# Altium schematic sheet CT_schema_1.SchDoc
size 403 x 336 mm
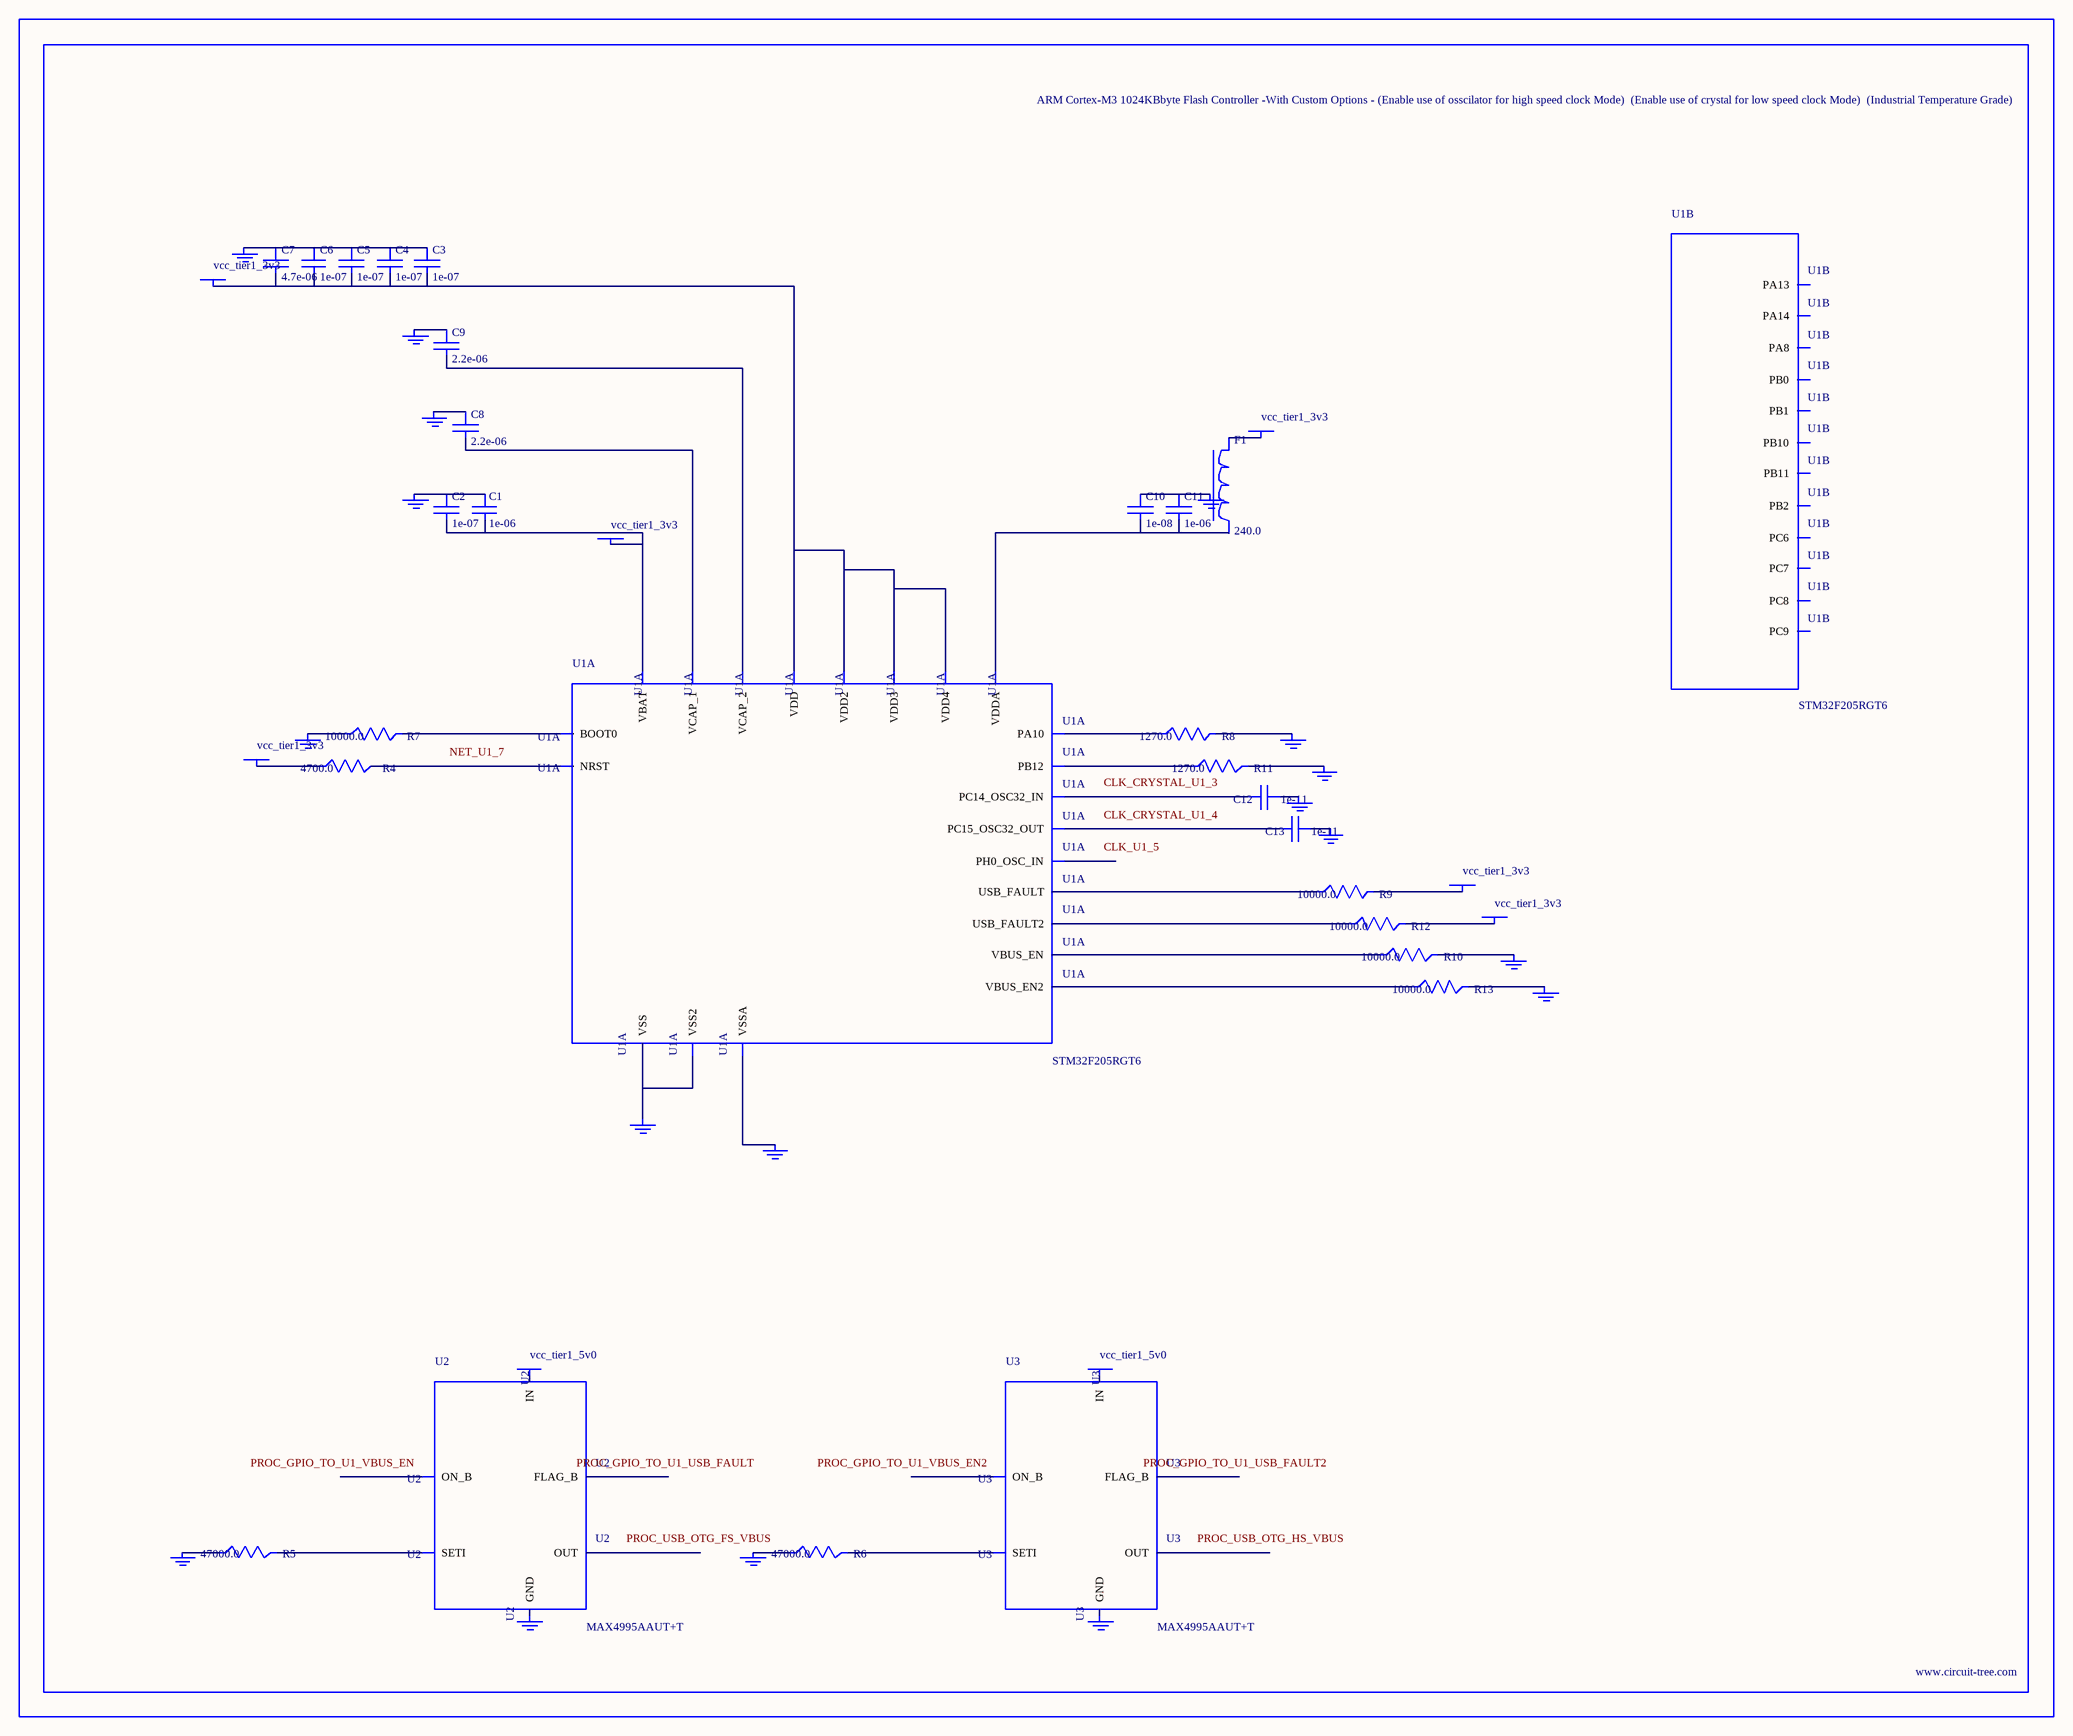
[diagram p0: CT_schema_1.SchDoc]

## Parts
BORDER0  (no value)
C1  1e-06  [C0603]
C2  1e-07  [C0603]
C3  1e-07  [C0603]
C4  1e-07  [C0603]
C5  1e-07  [C0603]
C6  1e-07  [C0603]
C7  4.7e-06  [C0603]
C8  2.2e-06  [C0603]
C9  2.2e-06  [C0603]
C10  1e-08  [C0603]
C11  1e-06  [C0603]
C12  1e-11  [C0402]
C13  1e-11  [C0402]
F1  240.0  [L0603]
GND_INSTANCE_0_0  (no value)
GND_INSTANCE_0_1  (no value)
GND_INSTANCE_0_2  (no value)
GND_INSTANCE_0_3  (no value)
GND_INSTANCE_0_4  (no value)
GND_INSTANCE_0_5  (no value)
GND_INSTANCE_0_6  (no value)
GND_INSTANCE_0_7  (no value)
GND_INSTANCE_0_8  (no value)
GND_INSTANCE_0_9  (no value)
GND_INSTANCE_0_10  (no value)
GND_INSTANCE_0_11  (no value)
GND_INSTANCE_0_12  (no value)
GND_INSTANCE_0_13  (no value)
GND_INSTANCE_0_14  (no value)
GND_INSTANCE_0_15  (no value)
GND_INSTANCE_0_16  (no value)
GND_INSTANCE_0_17  (no value)
POWER_INSTANCE_0_0  vcc_tier1_3v3
POWER_INSTANCE_0_1  vcc_tier1_3v3
POWER_INSTANCE_0_2  vcc_tier1_3v3
POWER_INSTANCE_0_3  vcc_tier1_3v3
POWER_INSTANCE_0_4  vcc_tier1_3v3
POWER_INSTANCE_0_5  vcc_tier1_3v3
POWER_INSTANCE_0_6  vcc_tier1_5v0
POWER_INSTANCE_0_7  vcc_tier1_5v0
R4  4700.0  [R0603]
R5  47000.0  [R0603]
R6  47000.0  [R0603]
R7  10000.0  [R0603]
R8  1270.0  [R0603]
R9  10000.0  [R0603]
R10  10000.0  [R0603]
R11  1270.0  [R0603]
R12  10000.0  [R0603]
R13  10000.0  [R0603]
U1  STM32F205RGT6  [LQFP64]  (parts A,B of 5)
U2  MAX4995AAUT+T  [SOT-23-6]
U3  MAX4995AAUT+T  [SOT-23-6]

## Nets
NetC1_1: C1.1 C2.1 GND_INSTANCE_0_0.0(GND)
NetC1_2: C1.2 C2.2 POWER_INSTANCE_0_0.0(PWR) U1.1(VBAT)
NetC3_1: C3.1 C4.1 C5.1 C6.1 C7.1 GND_INSTANCE_0_7.0(GND)
NetC3_2: C3.2 C4.2 C5.2 C6.2 C7.2 POWER_INSTANCE_0_4.0(PWR) U1.19(VDD) U1.32(VDD2) U1.48(VDD3) U1.64(VDD4)
NetC8_1: C8.1 GND_INSTANCE_0_8.0(GND)
NetC8_2: C8.2 U1.31(VCAP_1)
NetC9_1: C9.1 GND_INSTANCE_0_11.0(GND)
NetC9_2: C9.2 U1.47(VCAP_2)
NetC10_1: C10.1 C11.1 GND_INSTANCE_0_6.0(GND)
NetC10_2: C10.2 C11.2 U1.13(VDDA)
NetC12_1: C12.1 GND_INSTANCE_0_2.0(GND)
NetC12_2: C12.2 U1.3(PC14_OSC32_IN)
NetC13_1: C13.1 GND_INSTANCE_0_3.0(GND)
NetC13_2: C13.2 U1.4(PC15_OSC32_OUT)
NetF1_1: F1.1 POWER_INSTANCE_0_3.0(PWR)
NetGND_INSTANCE_0_1_0: GND_INSTANCE_0_1.0(GND) R10.2
NetGND_INSTANCE_0_4_0: GND_INSTANCE_0_4.0(GND) R13.2
NetGND_INSTANCE_0_5_0: GND_INSTANCE_0_5.0(GND) U1.12(VSSA)
NetGND_INSTANCE_0_9_0: GND_INSTANCE_0_9.0(GND) R11.2
NetGND_INSTANCE_0_10_0: GND_INSTANCE_0_10.0(GND) R8.2
NetGND_INSTANCE_0_12_0: GND_INSTANCE_0_12.0(GND) R7.1
NetGND_INSTANCE_0_13_0: GND_INSTANCE_0_13.0(GND) U1.18(VSS) U1.63(VSS2)
NetGND_INSTANCE_0_14_0: GND_INSTANCE_0_14.0(GND) R5.1
NetGND_INSTANCE_0_16_0: GND_INSTANCE_0_16.0(GND) R6.1
NetPOWER_INSTANCE_0_1_0: POWER_INSTANCE_0_1.0(PWR) R9.2
NetPOWER_INSTANCE_0_2_0: POWER_INSTANCE_0_2.0(PWR) R12.2
NetPOWER_INSTANCE_0_5_0: POWER_INSTANCE_0_5.0(PWR) R4.1
NetR4_2: R4.2 U1.7(NRST)
NetR5_2: R5.2 U2.3(SETI)
NetR6_2: R6.2 U3.3(SETI)
NetR7_2: R7.2 U1.60(BOOT0)
NetR8_1: R8.1 U1.43(PA10)
NetR9_1: R9.1 U1.6(USB_FAULT)
NetR10_1: R10.1 U1.2(VBUS_EN)
NetR11_1: R11.1 U1.33(PB12)
NetR12_1: R12.1 U1.9(USB_FAULT2)
NetR13_1: R13.1 U1.8(VBUS_EN2)

Not connected (* = marked no-connect by the designer): F1 2; GND_INSTANCE_0_15 0(GND); GND_INSTANCE_0_17 0(GND); POWER_INSTANCE_0_6 0(PWR); POWER_INSTANCE_0_7 0(PWR); U1 5(PH0_OSC_IN) 26(PB0) 27(PB1) 28(PB2) 29(PB10) 30(PB11) 37(PC6) 38(PC7) 39(PC8) 40(PC9) 41(PA8) 46(PA13) 49(PA14); U2 1(OUT) 2(GND) 4(ON_B) 5(IN) 6(FLAG_B); U3 1(OUT) 2(GND) 4(ON_B) 5(IN) 6(FLAG_B)

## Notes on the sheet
- Labels drawn without touching a wire or pin: CLK_CRYSTAL_U1_3, CLK_CRYSTAL_U1_4, CLK_U1_5, NET_U1_7, PROC_GPIO_TO_U1_USB_FAULT, PROC_GPIO_TO_U1_USB_FAULT2, PROC_GPIO_TO_U1_VBUS_EN, PROC_GPIO_TO_U1_VBUS_EN2, PROC_USB_OTG_FS_VBUS, PROC_USB_OTG_HS_VBUS

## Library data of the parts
BORDER0 = BORDER_PAGE0
C1 C11 = C0603C105K3RACTU
C2-C6 = 06035C104K4Z2A
C7 = GRM188R6YA475KE15D
C8 C9 = C0603C225K8RACTU
C10 = 06035C103K4Z2A
C12 C13 = C0402C100K3GACTU
F1 = Z0603C241ASMST
GND_INSTANCE_0_0-GND_INSTANCE_0_17 = GND
POWER_INSTANCE_0_0-POWER_INSTANCE_0_7 = PWR
R4 = RC0603JR-074K7L
R5 R6 = RC0603JR-0747KL
R7 R9 R10 R12 R13 = RC0603JR-0710KL
R8 R11 = RC0603FR-071K27L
